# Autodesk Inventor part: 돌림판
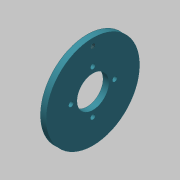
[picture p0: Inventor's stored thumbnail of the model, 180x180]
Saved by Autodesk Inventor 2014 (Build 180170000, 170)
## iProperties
Created: 2019-10
Part Number: 돌림판
Material: 스테인리스강
Document SubType Name: Modeling
Designer: mduedu
Density: 1 g/cm^3
Appearance: Cadet Blue
Author: mduedu
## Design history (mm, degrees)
sketch "스케치1" dims "d3" = 30
  geometry: C1 r 32 at (0, 0); C2 r 11 at (0, 0); C3 r 1.7 at (15, 0); C4 r 1.7 at (0, 15); C5 r 1.7 at (-15, 0); C6 r 1.7 at (0, -15); 2 further points
  constraints: 6 centre point, 3 coincident, 2 horizontal alignment, 11 other
  dimensions: "d0" = 64 diameter of C1; "d2" = 3.4 diameter of C3; "d4" = 22 diameter of C2; "d7" = 360 deg dimension on point (0, 0) C3.centre (derived)
extrude "돌출1" new body sketch "스케치1" distance "d9" = 4; taper "d10" = 0 deg
sketch "스케치2" dims "d11" = 54
  geometry: 3 further points
  constraints: 2 vertical alignment, 1 coincident, 2 other
hole "구멍1" sketch "스케치2" at (0, 27) diameter "d13" = 3.242; stored, may be unused: countersink angle "d17" = 90 deg, drill point angle "d19" = 118 deg; dims "d14" = 6, "d15" = 4, "d16" = 2, "d18" = 8
node "솔리드1"
